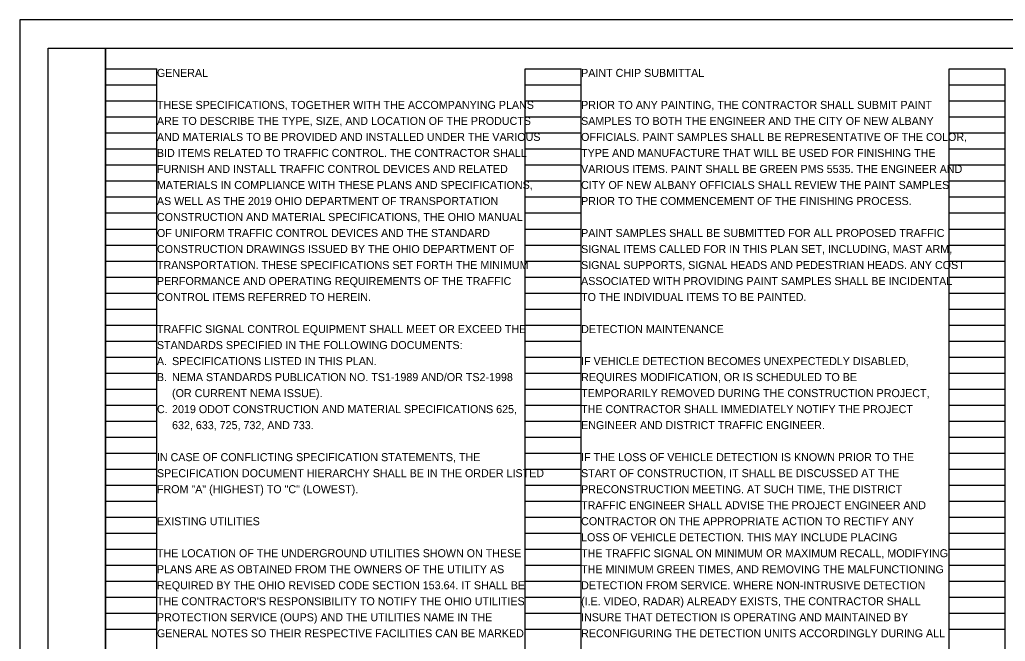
# Model space of a CAD drawing. Extents: x 0 to 34, y 0 to 22.
# Drawn here: x 0 to 17.24, y 11.13 to 22 of the extents above; entities that cross this region are included whole.
import ezdxf

# ---------------------------------------------------------------- set-up
doc = ezdxf.new("R2010")
doc.units = 0
for name, color, linetype in [('SH_Border', 7, 'Continuous'), ('SH_Cut_Line', 7, 'Continuous'), ('SH_Data', 7, 'Continuous'), ('SH_Text', 7, 'Continuous')]:
    doc.layers.add(name, color=color, linetype=linetype)

msp = doc.modelspace()

# ---------------------------------------------------------------- linework, layer by layer
at = {"layer": 'SH_Border'}
for points in [[(0.5, 21.5), (1.5, 21.5), (1.5, 0.5), (0.5, 0.5)], [(1.5, 21.5), (33.5, 21.5), (33.5, 0.5), (1.5, 0.5)]]:
    msp.add_lwpolyline(points, close=True, dxfattribs=at)
at = {"layer": 'SH_Cut_Line'}
msp.add_lwpolyline([(0, 0), (34, 0), (34, 22), (0, 22)], close=True, dxfattribs=at)
at = {"layer": 'SH_Data'}
for p, q in [((1.5, 0.98), (1.5, 21.14)), ((1.5, 21.14), (2.4, 21.14)), ((2.4, 0.98), (2.4, 21.14)), ((8.84, 0.98), (8.84, 21.14)), ((8.84, 21.14), (9.82, 21.14)), ((9.82, 0.98), (9.82, 21.14)), ((16.26, 0.98), (16.26, 21.14)), ((16.26, 21.14), (17.24, 21.14)), ((17.24, 0.98), (17.24, 21.14)), ((1.5, 20.86), (2.4, 20.86)), ((8.84, 20.86), (9.82, 20.86)), ((16.26, 20.86), (17.24, 20.86)), ((1.5, 20.58), (2.4, 20.58)), ((8.84, 20.58), (9.82, 20.58)), ((16.26, 20.58), (17.24, 20.58)), ((1.5, 20.3), (2.4, 20.3)), ((8.84, 20.3), (9.82, 20.3)), ((16.26, 20.3), (17.24, 20.3)), ((1.5, 20.02), (2.4, 20.02)), ((8.84, 20.02), (9.82, 20.02)), ((16.26, 20.02), (17.24, 20.02)), ((1.5, 19.74), (2.4, 19.74)), ((8.84, 19.74), (9.82, 19.74)), ((16.26, 19.74), (17.24, 19.74)), ((1.5, 19.46), (2.4, 19.46)), ((8.84, 19.46), (9.82, 19.46)), ((16.26, 19.46), (17.24, 19.46)), ((1.5, 19.18), (2.4, 19.18)), ((8.84, 19.18), (9.82, 19.18)), ((16.26, 19.18), (17.24, 19.18)), ((1.5, 18.9), (2.4, 18.9)), ((8.84, 18.9), (9.82, 18.9)), ((16.26, 18.9), (17.24, 18.9)), ((1.5, 18.62), (2.4, 18.62)), ((8.84, 18.62), (9.82, 18.62)), ((16.26, 18.62), (17.24, 18.62)), ((1.5, 18.34), (2.4, 18.34)), ((8.84, 18.34), (9.82, 18.34)), ((16.26, 18.34), (17.24, 18.34)), ((1.5, 18.06), (2.4, 18.06)), ((8.84, 18.06), (9.82, 18.06)), ((16.26, 18.06), (17.24, 18.06)), ((1.5, 17.78), (2.4, 17.78)), ((8.84, 17.78), (9.82, 17.78)), ((16.26, 17.78), (17.24, 17.78)), ((1.5, 17.5), (2.4, 17.5)), ((8.84, 17.5), (9.82, 17.5)), ((16.26, 17.5), (17.24, 17.5)), ((1.5, 17.22), (2.4, 17.22)), ((8.84, 17.22), (9.82, 17.22)), ((16.26, 17.22), (17.24, 17.22)), ((1.5, 16.94), (2.4, 16.94)), ((8.84, 16.94), (9.82, 16.94)), ((16.26, 16.94), (17.24, 16.94)), ((1.5, 16.66), (2.4, 16.66)), ((8.84, 16.66), (9.82, 16.66)), ((16.26, 16.66), (17.24, 16.66)), ((1.5, 16.38), (2.4, 16.38)), ((8.84, 16.38), (9.82, 16.38)), ((16.26, 16.38), (17.24, 16.38)), ((1.5, 16.1), (2.4, 16.1)), ((8.84, 16.1), (9.82, 16.1)), ((16.26, 16.1), (17.24, 16.1)), ((1.5, 15.82), (2.4, 15.82)), ((8.84, 15.82), (9.82, 15.82)), ((16.26, 15.82), (17.24, 15.82)), ((1.5, 15.54), (2.4, 15.54)), ((8.84, 15.54), (9.82, 15.54)), ((16.26, 15.54), (17.24, 15.54)), ((1.5, 15.26), (2.4, 15.26)), ((8.84, 15.26), (9.82, 15.26)), ((16.26, 15.26), (17.24, 15.26)), ((1.5, 14.98), (2.4, 14.98)), ((8.84, 14.98), (9.82, 14.98)), ((16.26, 14.98), (17.24, 14.98)), ((1.5, 14.7), (2.4, 14.7)), ((8.84, 14.7), (9.82, 14.7)), ((16.26, 14.7), (17.24, 14.7)), ((1.5, 14.42), (2.4, 14.42)), ((8.84, 14.42), (9.82, 14.42)), ((16.26, 14.42), (17.24, 14.42)), ((1.5, 14.14), (2.4, 14.14)), ((8.84, 14.14), (9.82, 14.14)), ((16.26, 14.14), (17.24, 14.14)), ((1.5, 13.86), (2.4, 13.86)), ((8.84, 13.86), (9.82, 13.86)), ((16.26, 13.86), (17.24, 13.86)), ((1.5, 13.58), (2.4, 13.58)), ((8.84, 13.58), (9.82, 13.58)), ((16.26, 13.58), (17.24, 13.58)), ((1.5, 13.3), (2.4, 13.3)), ((8.84, 13.3), (9.82, 13.3)), ((16.26, 13.3), (17.24, 13.3)), ((1.5, 13.02), (2.4, 13.02)), ((8.84, 13.02), (9.82, 13.02)), ((16.26, 13.02), (17.24, 13.02)), ((1.5, 12.74), (2.4, 12.74)), ((8.84, 12.74), (9.82, 12.74)), ((16.26, 12.74), (17.24, 12.74)), ((1.5, 12.46), (2.4, 12.46)), ((8.84, 12.46), (9.82, 12.46)), ((16.26, 12.46), (17.24, 12.46)), ((1.5, 12.18), (2.4, 12.18)), ((8.84, 12.18), (9.82, 12.18)), ((16.26, 12.18), (17.24, 12.18)), ((1.5, 11.9), (2.4, 11.9)), ((8.84, 11.9), (9.82, 11.9)), ((16.26, 11.9), (17.24, 11.9)), ((1.5, 11.62), (2.4, 11.62)), ((8.84, 11.62), (9.82, 11.62)), ((16.26, 11.62), (17.24, 11.62)), ((1.5, 11.34), (2.4, 11.34)), ((8.84, 11.34), (9.82, 11.34)), ((16.26, 11.34), (17.24, 11.34))]:
    msp.add_line(p, q, dxfattribs=at)

# ---------------------------------------------------------------- texts
at = {"layer": 'SH_Text'}
for s, p in [('GENERAL', (2.4, 21)), ('PAINT CHIP SUBMITTAL', (9.82, 21)), ('THESE SPECIFICATIONS, TOGETHER WITH THE ACCOMPANYING PLANS ', (2.4, 20.44)), ('PRIOR TO ANY PAINTING, THE CONTRACTOR SHALL SUBMIT PAINT ', (9.82, 20.44)), ('ARE TO DESCRIBE THE TYPE, SIZE, AND LOCATION OF THE PRODUCTS ', (2.4, 20.16)), ('SAMPLES TO BOTH THE ENGINEER AND THE CITY OF NEW ALBANY ', (9.82, 20.16)), ('AND MATERIALS TO BE PROVIDED AND INSTALLED UNDER THE VARIOUS ', (2.4, 19.88)), ('OFFICIALS. PAINT SAMPLES SHALL BE REPRESENTATIVE OF THE COLOR, ', (9.82, 19.88)), ('BID ITEMS RELATED TO TRAFFIC CONTROL. THE CONTRACTOR SHALL ', (2.4, 19.6)), ('TYPE AND MANUFACTURE THAT WILL BE USED FOR FINISHING THE ', (9.82, 19.6)), ('FURNISH AND INSTALL TRAFFIC CONTROL DEVICES AND RELATED ', (2.4, 19.32)), ('VARIOUS ITEMS. PAINT SHALL BE GREEN PMS 5535. THE ENGINEER AND ', (9.82, 19.32)), ('MATERIALS IN COMPLIANCE WITH THESE PLANS AND SPECIFICATIONS, ', (2.4, 19.04)), ('CITY OF NEW ALBANY OFFICIALS SHALL REVIEW THE PAINT SAMPLES ', (9.82, 19.04)), ('AS WELL AS THE 2019 OHIO DEPARTMENT OF TRANSPORTATION ', (2.4, 18.76)), ('PRIOR TO THE COMMENCEMENT OF THE FINISHING PROCESS.', (9.82, 18.76)), ('CONSTRUCTION AND MATERIAL SPECIFICATIONS, THE OHIO MANUAL ', (2.4, 18.48)), ('OF UNIFORM TRAFFIC CONTROL DEVICES AND THE STANDARD ', (2.4, 18.2)), ('PAINT SAMPLES SHALL BE SUBMITTED FOR ALL PROPOSED TRAFFIC ', (9.82, 18.2)), ('CONSTRUCTION DRAWINGS ISSUED BY THE OHIO DEPARTMENT OF ', (2.4, 17.92)), ('SIGNAL ITEMS CALLED FOR IN THIS PLAN SET, INCLUDING, MAST ARM, ', (9.82, 17.92)), ('TRANSPORTATION. THESE SPECIFICATIONS SET FORTH THE MINIMUM ', (2.4, 17.64)), ('SIGNAL SUPPORTS, SIGNAL HEADS AND PEDESTRIAN HEADS. ANY COST ', (9.82, 17.64)), ('PERFORMANCE AND OPERATING REQUIREMENTS OF THE TRAFFIC ', (2.4, 17.36)), ('ASSOCIATED WITH PROVIDING PAINT SAMPLES SHALL BE INCIDENTAL ', (9.82, 17.36)), ('CONTROL ITEMS REFERRED TO HEREIN.', (2.4, 17.08)), ('TO THE INDIVIDUAL ITEMS TO BE PAINTED.', (9.82, 17.08)), ('TRAFFIC SIGNAL CONTROL EQUIPMENT SHALL MEET OR EXCEED THE ', (2.4, 16.52)), ('DETECTION MAINTENANCE', (9.82, 16.52)), ('STANDARDS SPECIFIED IN THE FOLLOWING DOCUMENTS:', (2.4, 16.24)), ('A. ', (2.4, 15.96)), ('SPECIFICATIONS LISTED IN THIS PLAN.', (2.665, 15.96)), ('IF VEHICLE DETECTION BECOMES UNEXPECTEDLY DISABLED,', (9.82, 15.96)), ('B. ', (2.4, 15.68)), ('NEMA STANDARDS PUBLICATION NO. TS1-1989 AND/OR TS2-1998 ', (2.665, 15.68)), ('REQUIRES MODIFICATION, OR IS SCHEDULED TO BE', (9.82, 15.68)), ('(OR CURRENT NEMA ISSUE).', (2.665, 15.4)), ('TEMPORARILY REMOVED DURING THE CONSTRUCTION PROJECT,', (9.82, 15.4)), ('C. ', (2.4, 15.12)), ('2019 ODOT CONSTRUCTION AND MATERIAL SPECIFICATIONS 625, ', (2.665, 15.12)), ('THE CONTRACTOR SHALL IMMEDIATELY NOTIFY THE PROJECT', (9.82, 15.12)), ('632, 633, 725, 732, AND 733.', (2.665, 14.84)), ('ENGINEER AND DISTRICT TRAFFIC ENGINEER.', (9.82, 14.84)), ('IN CASE OF CONFLICTING SPECIFICATION STATEMENTS, THE ', (2.4, 14.28)), ('IF THE LOSS OF VEHICLE DETECTION IS KNOWN PRIOR TO THE', (9.82, 14.28)), ('SPECIFICATION DOCUMENT HIERARCHY SHALL BE IN THE ORDER LISTED ', (2.4, 14)), ('START OF CONSTRUCTION, IT SHALL BE DISCUSSED AT THE', (9.82, 14)), ('FROM "A" (HIGHEST) TO "C" (LOWEST).', (2.4, 13.72)), ('PRECONSTRUCTION MEETING. AT SUCH TIME, THE DISTRICT', (9.82, 13.72)), ('TRAFFIC ENGINEER SHALL ADVISE THE PROJECT ENGINEER AND', (9.82, 13.44)), ('EXISTING UTILITIES', (2.4, 13.16)), ('CONTRACTOR ON THE APPROPRIATE ACTION TO RECTIFY ANY', (9.82, 13.16)), ('LOSS OF VEHICLE DETECTION. THIS MAY INCLUDE PLACING', (9.82, 12.88)), ('THE LOCATION OF THE UNDERGROUND UTILITIES SHOWN ON THESE ', (2.4, 12.6)), ('THE TRAFFIC SIGNAL ON MINIMUM OR MAXIMUM RECALL, MODIFYING', (9.82, 12.6)), ('PLANS ARE AS OBTAINED FROM THE OWNERS OF THE UTILITY AS ', (2.4, 12.32)), ('THE MINIMUM GREEN TIMES, AND REMOVING THE MALFUNCTIONING', (9.82, 12.32)), ('REQUIRED BY THE OHIO REVISED CODE SECTION 153.64. IT SHALL BE ', (2.4, 12.04)), ('DETECTION FROM SERVICE. WHERE NON-INTRUSIVE DETECTION', (9.82, 12.04)), ("THE CONTRACTOR'S RESPONSIBILITY TO NOTIFY THE OHIO UTILITIES ", (2.4, 11.76)), ('(I.E. VIDEO, RADAR) ALREADY EXISTS, THE CONTRACTOR SHALL', (9.82, 11.76)), ('PROTECTION SERVICE (OUPS) AND THE UTILITIES NAME IN THE ', (2.4, 11.48)), ('INSURE THAT DETECTION IS OPERATING AND MAINTAINED BY', (9.82, 11.48)), ('GENERAL NOTES SO THEIR RESPECTIVE FACILITIES CAN BE MARKED ', (2.4, 11.2)), ('RECONFIGURING THE DETECTION UNITS ACCORDINGLY DURING ALL', (9.82, 11.2))]:
    msp.add_text(s, height=0.14, dxfattribs=at).set_placement(p)

doc.saveas('drawing.dxf')
